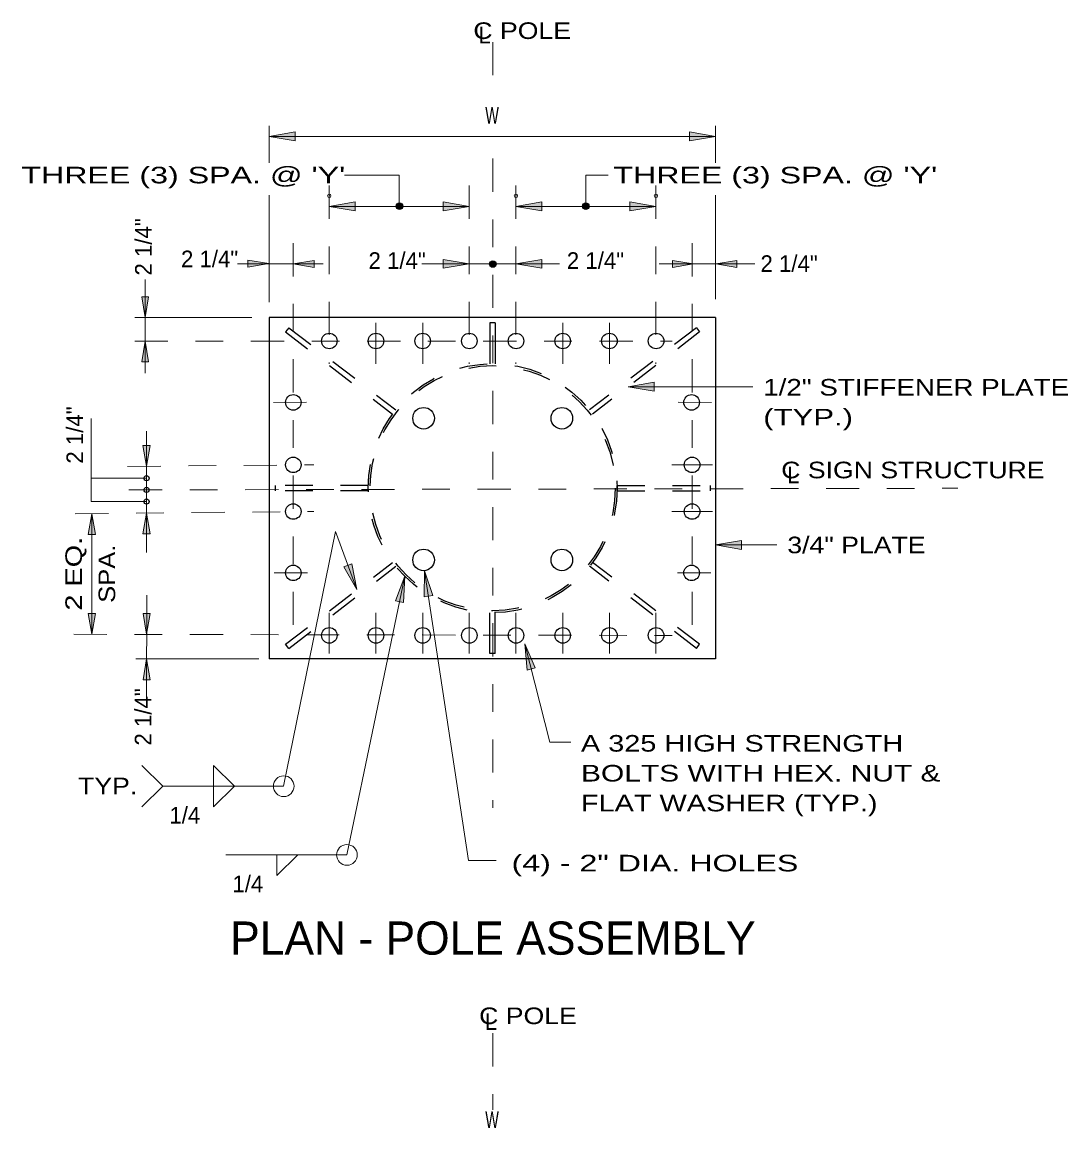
# Model space of a CAD drawing. Extents: x -34838.8 to -34832.2, y -181512.9 to -181502.8.
# Drawn here: x -34837.172 to -34833.392, y -181506.845 to -181502.848 of the extents above; entities that cross this region are included whole.
import ezdxf
from ezdxf.enums import TextEntityAlignment as Align

# ---------------------------------------------------------------- set-up
doc = ezdxf.new("R2010")
doc.units = 0
doc.header["$LTSCALE"] = 0.024
doc.header["$PDMODE"] = 32
doc.header["$PDSIZE"] = 0.012
doc.linetypes.add('DOT_DASHED', pattern=[7.7, 5, -1.2, 0.3, -1.2])
doc.linetypes.add('MEDIUM_DASHED', pattern=[4.5, 3, -1.5])
doc.layers.add('1', color=7, linetype='Continuous', lineweight=25)
doc.layers.add('10', color=7, linetype='Continuous', lineweight=13)
doc.layers.add('12', color=7, linetype='Continuous')
doc.layers.add('13', color=7, linetype='Continuous')

msp = doc.modelspace()

# ---------------------------------------------------------------- hatches: boundary and pattern name
at = {"layer": '1'}
for points in [[(-34835.79609, -181503.51347, 1), (-34835.81953, -181503.51347, 1)], [(-34835.12309, -181503.51347, 1), (-34835.14653, -181503.51347, 1)], [(-34835.45909, -181503.72247, 1), (-34835.48253, -181503.72247, 1)]]:
    msp.add_hatch(color=256, dxfattribs=at).paths.add_polyline_path(points)
at = {"layer": '10'}
for points in [[(-34836.185, -181503.277), (-34836.185, -181503.245), (-34836.279, -181503.261)], [(-34834.76, -181503.245), (-34834.76, -181503.277), (-34834.666, -181503.261)], [(-34835.968, -181503.53), (-34835.968, -181503.498), (-34836.062, -181503.514)], [(-34835.65, -181503.498), (-34835.65, -181503.53), (-34835.556, -181503.514)], [(-34835.293, -181503.53), (-34835.293, -181503.498), (-34835.387, -181503.514)], [(-34835.293, -181503.53), (-34835.293, -181503.498), (-34835.387, -181503.514)], [(-34834.975, -181503.498), (-34834.975, -181503.53), (-34834.881, -181503.514)], [(-34836.356, -181503.734), (-34836.281, -181503.721), (-34836.356, -181503.709)], [(-34836.117, -181503.71), (-34836.192, -181503.722), (-34836.117, -181503.735)], [(-34835.65, -181503.706), (-34835.65, -181503.738), (-34835.556, -181503.722)], [(-34835.293, -181503.738), (-34835.293, -181503.706), (-34835.387, -181503.722)], [(-34834.821, -181503.735), (-34834.746, -181503.722), (-34834.821, -181503.71)], [(-34834.589, -181503.71), (-34834.664, -181503.722), (-34834.589, -181503.735)], [(-34836.74, -181503.841), (-34836.728, -181503.916), (-34836.715, -181503.841)], [(-34836.715, -181504.076), (-34836.728, -181504.001), (-34836.74, -181504.076)], [(-34834.887, -181504.182), (-34834.887, -181504.15), (-34834.981, -181504.166)], [(-34834.887, -181504.182), (-34834.887, -181504.15), (-34834.981, -181504.166)], [(-34836.71, -181504.378), (-34836.736, -181504.378), (-34836.723, -181504.453)], [(-34836.933, -181504.7), (-34836.907, -181504.7), (-34836.92, -181504.625)], [(-34836.736, -181504.698), (-34836.71, -181504.698), (-34836.723, -181504.623)], [(-34834.572, -181504.754), (-34834.572, -181504.722), (-34834.666, -181504.738)], [(-34835.98, -181504.806), (-34836.009, -181504.817), (-34835.962, -181504.899)], [(-34835.719, -181504.926), (-34835.688, -181504.921), (-34835.718, -181504.831)], [(-34835.823, -181504.94), (-34835.793, -181504.946), (-34835.789, -181504.851)], [(-34836.907, -181504.986), (-34836.933, -181504.986), (-34836.92, -181505.061)], [(-34836.71, -181504.986), (-34836.723, -181505.061), (-34836.735, -181504.986)], [(-34835.347, -181505.19), (-34835.317, -181505.182), (-34835.355, -181505.095)], [(-34836.735, -181505.225), (-34836.723, -181505.15), (-34836.71, -181505.225)]]:
    msp.add_hatch(color=256, dxfattribs=at).paths.add_polyline_path(points)

# ---------------------------------------------------------------- linework, layer by layer
at = {"layer": '1', "linetype": 'DOT_DASHED', "lineweight": 13}
for p, q in [((-34835.471, -181502.92), (-34835.471, -181503.094)), ((-34835.471, -181503.341), (-34835.471, -181505.688)), ((-34836.062, -181503.439), (-34836.062, -181504.083)), ((-34835.556, -181503.439), (-34835.556, -181504.083)), ((-34835.387, -181503.439), (-34835.387, -181504.083)), ((-34834.881, -181503.439), (-34834.881, -181504.083)), ((-34836.192, -181503.647), (-34836.192, -181505.042)), ((-34834.75, -181503.647), (-34834.75, -181505.042)), ((-34836.765, -181504.001), (-34834.822, -181504.001)), ((-34836.264, -181504.223), (-34836.118, -181504.222)), ((-34834.68, -181504.223), (-34834.826, -181504.222)), ((-34836.791, -181504.454), (-34836.118, -181504.448)), ((-34836.786, -181504.539), (-34833.79, -181504.533)), ((-34836.98, -181504.625), (-34836.118, -181504.617)), ((-34836.261, -181504.839), (-34836.118, -181504.838)), ((-34834.683, -181504.839), (-34834.826, -181504.838)), ((-34836.986, -181505.061), (-34834.822, -181505.065)), ((-34835.471, -181506.503), (-34835.471, -181506.78))]:
    msp.add_line(p, q, dxfattribs=at)
at = {"layer": '1'}
for p, q in [((-34834.666, -181503.916), (-34836.279, -181503.916)), ((-34836.279, -181503.916), (-34836.279, -181505.149)), ((-34834.666, -181503.916), (-34834.666, -181505.149)), ((-34836.208, -181503.953), (-34836.22, -181503.968)), ((-34835.481, -181503.935), (-34835.481, -181504.083)), ((-34835.462, -181503.935), (-34835.481, -181503.935)), ((-34835.462, -181503.935), (-34835.462, -181504.083)), ((-34834.734, -181503.953), (-34834.723, -181503.968)), ((-34836.258, -181504.523), (-34836.258, -181504.542)), ((-34835.921, -181504.542), (-34835.921, -181504.523)), ((-34835.021, -181504.542), (-34835.021, -181504.523)), ((-34834.685, -181504.523), (-34834.685, -181504.542)), ((-34835.481, -181505.13), (-34835.481, -181504.983)), ((-34835.462, -181505.13), (-34835.462, -181504.983)), ((-34836.208, -181505.112), (-34836.22, -181505.097)), ((-34834.734, -181505.112), (-34834.723, -181505.097)), ((-34834.666, -181505.149), (-34836.279, -181505.149)), ((-34835.462, -181505.13), (-34835.481, -181505.13))]:
    msp.add_line(p, q, dxfattribs=at)
at = {"layer": '1', "linetype": 'MEDIUM_DASHED'}
for p, q in [((-34836.208, -181503.953), (-34835.821, -181504.25)), ((-34834.734, -181503.953), (-34835.121, -181504.25)), ((-34836.22, -181503.968), (-34835.833, -181504.265)), ((-34834.723, -181503.968), (-34835.11, -181504.265)), ((-34835.921, -181504.523), (-34836.258, -181504.523)), ((-34835.021, -181504.523), (-34834.685, -181504.523)), ((-34835.921, -181504.542), (-34836.258, -181504.542)), ((-34835.021, -181504.542), (-34834.685, -181504.542)), ((-34836.22, -181505.097), (-34835.833, -181504.801)), ((-34834.723, -181505.097), (-34835.11, -181504.801)), ((-34836.208, -181505.112), (-34835.821, -181504.815)), ((-34834.734, -181505.112), (-34835.121, -181504.815))]:
    msp.add_line(p, q, dxfattribs=at)
at = {"layer": '1', "lineweight": 13}
for p, q in [((-34835.893, -181503.935), (-34835.893, -181504.083)), ((-34835.724, -181503.935), (-34835.724, -181504.083)), ((-34835.218, -181503.935), (-34835.218, -181504.083)), ((-34835.049, -181503.935), (-34835.049, -181504.083)), ((-34834.824, -181504.448), (-34834.676, -181504.448)), ((-34834.824, -181504.617), (-34834.676, -181504.617)), ((-34836.062, -181505.13), (-34836.062, -181504.983)), ((-34835.893, -181505.13), (-34835.893, -181504.983)), ((-34835.724, -181505.13), (-34835.724, -181504.983)), ((-34835.556, -181505.13), (-34835.556, -181504.983)), ((-34835.387, -181505.13), (-34835.387, -181504.983)), ((-34835.218, -181505.13), (-34835.218, -181504.983)), ((-34835.049, -181505.13), (-34835.049, -181504.983)), ((-34834.881, -181505.13), (-34834.881, -181504.983))]:
    msp.add_line(p, q, dxfattribs=at)
at = {"layer": '1'}
for centre, radius in [((-34835.80781, -181503.51347), 0.01172), ((-34835.13481, -181503.51347), 0.01172), ((-34835.47081, -181503.72247), 0.01172), ((-34836.06178, -181504.00071), 0.02813), ((-34835.89302, -181504.00071), 0.02813), ((-34835.72428, -181504.00071), 0.02813), ((-34835.55552, -181504.00071), 0.02813), ((-34835.38677, -181504.00071), 0.02813), ((-34835.21803, -181504.00071), 0.02813), ((-34835.04927, -181504.00071), 0.02813), ((-34834.88053, -181504.00071), 0.02813), ((-34836.19198, -181504.22264), 0.02813), ((-34834.75203, -181504.22264), 0.02813), ((-34835.721, -181504.28), 0.039), ((-34835.221, -181504.28), 0.039), ((-34836.19198, -181504.44839), 0.02813), ((-34834.75032, -181504.44839), 0.02813), ((-34836.72267, -181504.49657), 0.00937), ((-34836.72267, -181504.53876), 0.00937), ((-34836.72267, -181504.58095), 0.00937), ((-34836.19198, -181504.61714), 0.02813), ((-34834.75032, -181504.61714), 0.02813), ((-34835.721, -181504.792), 0.039), ((-34835.221, -181504.792), 0.039), ((-34836.19198, -181504.83889), 0.02813), ((-34834.75203, -181504.83889), 0.02813), ((-34836.06178, -181505.06481), 0.02813), ((-34835.89302, -181505.06481), 0.02813), ((-34835.72428, -181505.06481), 0.02813), ((-34835.55552, -181505.06481), 0.02813), ((-34835.38677, -181505.06481), 0.02813), ((-34835.21803, -181505.06481), 0.02813), ((-34835.04927, -181505.06481), 0.02813), ((-34834.88053, -181505.06481), 0.02813)]:
    msp.add_circle(centre, radius, dxfattribs=at)
at = {"layer": '1', "linetype": 'MEDIUM_DASHED'}
for radius in [0.45, 0.44295]:
    msp.add_circle((-34835.47115, -181504.53276), radius, dxfattribs=at)
at = {"layer": '10'}
for p, q in [((-34836.279, -181503.357), (-34836.279, -181503.223)), ((-34834.666, -181503.357), (-34834.666, -181503.223)), ((-34834.666, -181503.261), (-34836.279, -181503.261)), ((-34836.007, -181503.401), (-34835.809, -181503.401)), ((-34835.809, -181503.514), (-34835.809, -181503.401)), ((-34835.134, -181503.514), (-34835.134, -181503.401)), ((-34835.134, -181503.401), (-34835.054, -181503.401)), ((-34836.279, -181503.474), (-34836.279, -181503.86)), ((-34834.666, -181503.474), (-34834.666, -181503.849)), ((-34836.062, -181503.514), (-34835.556, -181503.514)), ((-34835.556, -181503.495), (-34835.556, -181503.551)), ((-34835.387, -181503.514), (-34834.881, -181503.514)), ((-34836.394, -181503.722), (-34836.084, -181503.722)), ((-34835.727, -181503.722), (-34835.556, -181503.722)), ((-34835.556, -181503.688), (-34835.556, -181503.685)), ((-34835.556, -181503.722), (-34835.387, -181503.722)), ((-34835.387, -181503.688), (-34835.387, -181503.685)), ((-34835.229, -181503.722), (-34835.387, -181503.722)), ((-34834.869, -181503.722), (-34834.523, -181503.722)), ((-34836.728, -181503.778), (-34836.728, -181504.117)), ((-34836.342, -181503.916), (-34836.765, -181503.916)), ((-34836.923, -181504.281), (-34836.923, -181504.581)), ((-34836.723, -181504.327), (-34836.723, -181504.539)), ((-34836.92, -181504.497), (-34836.723, -181504.497)), ((-34836.723, -181504.765), (-34836.723, -181504.539)), ((-34836.923, -181504.581), (-34836.723, -181504.581)), ((-34836.92, -181504.625), (-34836.92, -181505.061)), ((-34835.789, -181504.851), (-34835.998, -181505.858)), ((-34836.723, -181505.289), (-34836.722, -181504.919)), ((-34836.317, -181505.15), (-34836.761, -181505.15)), ((-34836.723, -181505.288), (-34836.723, -181505.171)), ((-34836.739, -181505.535), (-34836.664, -181505.61)), ((-34836.48, -181505.535), (-34836.405, -181505.61)), ((-34836.739, -181505.685), (-34836.664, -181505.61)), ((-34836.664, -181505.61), (-34836.227, -181505.61)), ((-34836.436, -181505.858), (-34835.998, -181505.858))]:
    msp.add_line(p, q, dxfattribs=at)
for points in [[(-34836.185, -181503.277), (-34836.185, -181503.245), (-34836.279, -181503.261)], [(-34834.76, -181503.245), (-34834.76, -181503.277), (-34834.666, -181503.261)], [(-34835.968, -181503.53), (-34835.968, -181503.498), (-34836.062, -181503.514)], [(-34835.65, -181503.498), (-34835.65, -181503.53), (-34835.556, -181503.514)], [(-34835.293, -181503.53), (-34835.293, -181503.498), (-34835.387, -181503.514)], [(-34835.293, -181503.53), (-34835.293, -181503.498), (-34835.387, -181503.514)], [(-34834.975, -181503.498), (-34834.975, -181503.53), (-34834.881, -181503.514)], [(-34836.356, -181503.734), (-34836.281, -181503.721), (-34836.356, -181503.709)], [(-34836.117, -181503.71), (-34836.192, -181503.722), (-34836.117, -181503.735)], [(-34835.65, -181503.706), (-34835.65, -181503.738), (-34835.556, -181503.722)], [(-34835.293, -181503.738), (-34835.293, -181503.706), (-34835.387, -181503.722)], [(-34834.821, -181503.735), (-34834.746, -181503.722), (-34834.821, -181503.71)], [(-34834.589, -181503.71), (-34834.664, -181503.722), (-34834.589, -181503.735)], [(-34836.74, -181503.841), (-34836.728, -181503.916), (-34836.715, -181503.841)], [(-34836.715, -181504.076), (-34836.728, -181504.001), (-34836.74, -181504.076)], [(-34834.887, -181504.182), (-34834.887, -181504.15), (-34834.981, -181504.166)], [(-34834.887, -181504.182), (-34834.887, -181504.15), (-34834.981, -181504.166)], [(-34836.71, -181504.378), (-34836.736, -181504.378), (-34836.723, -181504.453)], [(-34836.933, -181504.7), (-34836.907, -181504.7), (-34836.92, -181504.625)], [(-34836.736, -181504.698), (-34836.71, -181504.698), (-34836.723, -181504.623)], [(-34834.572, -181504.754), (-34834.572, -181504.722), (-34834.666, -181504.738)], [(-34835.98, -181504.806), (-34836.009, -181504.817), (-34835.962, -181504.899)], [(-34835.719, -181504.926), (-34835.688, -181504.921), (-34835.718, -181504.831)], [(-34835.823, -181504.94), (-34835.793, -181504.946), (-34835.789, -181504.851)], [(-34836.907, -181504.986), (-34836.933, -181504.986), (-34836.92, -181505.061)], [(-34836.71, -181504.986), (-34836.723, -181505.061), (-34836.735, -181504.986)], [(-34835.347, -181505.19), (-34835.317, -181505.182), (-34835.355, -181505.095)], [(-34836.735, -181505.225), (-34836.723, -181505.15), (-34836.71, -181505.225)]]:
    msp.add_lwpolyline(points, close=True, dxfattribs=at)
for points in [[(-34834.981, -181504.166), (-34834.681, -181504.166), (-34834.531, -181504.166)], [(-34835.962, -181504.899), (-34836.04, -181504.689), (-34836.227, -181505.61)], [(-34834.666, -181504.738), (-34834.444, -181504.738), (-34834.444, -181504.738)], [(-34835.718, -181504.831), (-34835.558, -181505.879), (-34835.458, -181505.879)], [(-34835.355, -181505.095), (-34835.264, -181505.451), (-34835.189, -181505.451)], [(-34836.48, -181505.535), (-34836.48, -181505.685), (-34836.405, -181505.61)], [(-34836.251, -181505.858), (-34836.251, -181505.933), (-34836.176, -181505.858)]]:
    msp.add_lwpolyline(points, dxfattribs=at)
for centre in [(-34836.22661, -181505.60986), (-34835.99803, -181505.85825)]:
    msp.add_circle(centre, 0.0375, dxfattribs=at)
for p in [(-34836.062, -181503.476), (-34835.387, -181503.476), (-34834.881, -181503.476)]:
    msp.add_point(p, dxfattribs=at)

# ---------------------------------------------------------------- texts
at = {"layer": '12'}
msp.add_text('PLAN - POLE ASSEMBLY', height=0.12, dxfattribs=at).set_placement((-34835.4705, -181506.219), align=Align.CENTER)
at = {"layer": '13', "width": 1.2}
for s, p in [('C POLE', (-34835.188, -181502.909)), ('TYP.', (-34836.756, -181505.639)), ('C POLE', (-34835.167, -181506.47))]:
    msp.add_text(s, height=0.06, dxfattribs=at).set_placement(p, align=Align.RIGHT)
at = {"layer": '13'}
for p in [(-34835.478, -181502.925), (-34835.455, -181506.491)]:
    msp.add_text('L', height=0.06, dxfattribs=at).set_placement(p, align=Align.RIGHT)
for s, width, p in [('W', 0.65, (-34835.498, -181503.215)), ("THREE (3) SPA. @ 'Y'", 1.45, (-34837.175, -181503.431)), ("THREE (3) SPA. @ 'Y'", 1.45, (-34835.035, -181503.431)), ('1/2" STIFFENER PLATE', 1.25, (-34834.493, -181504.198)), ('(TYP.)', 1.4, (-34834.493, -181504.306)), ('C SIGN STRUCTURE', 1.2, (-34834.428, -181504.497)), ('3/4" PLATE', 1.2, (-34834.406, -181504.768)), ('A 325 HIGH STRENGTH ', 1.3, (-34835.152, -181505.485)), ('BOLTS WITH HEX. NUT & ', 1.35, (-34835.152, -181505.593)), ('FLAT WASHER (TYP.)', 1.3, (-34835.152, -181505.701)), ('(4) - 2" DIA. HOLES', 1.45, (-34835.403, -181505.918)), ('W', 0.65, (-34835.498, -181506.845))]:
    msp.add_text(s, height=0.06, dxfattribs=dict(at, width=width)).set_placement(p)
for p in [(-34836.704, -181503.764), (-34836.952, -181504.444), (-34836.705, -181505.463)]:
    msp.add_text('2 1/4"', height=0.06, rotation=90, dxfattribs=at).set_placement(p)
for s, p in [('2 1/4"', (-34836.598, -181503.734)), ('2 1/4"', (-34835.92, -181503.74)), ('2 1/4"', (-34835.203, -181503.74)), ('2 1/4"', (-34834.503, -181503.751)), ('L', (-34834.407, -181504.515)), ('1/4', (-34836.64, -181505.745)), ('1/4', (-34836.412, -181505.993))]:
    msp.add_text(s, height=0.06, dxfattribs=at).set_placement(p)
for s, width, p in [('2 EQ.', 1.3, (-34836.956, -181504.842)), ('SPA.', 1.15, (-34836.836, -181504.842))]:
    msp.add_text(s, height=0.06, rotation=90, dxfattribs=dict(at, width=width)).set_placement(p, align=Align.CENTER)

doc.saveas('drawing.dxf')
